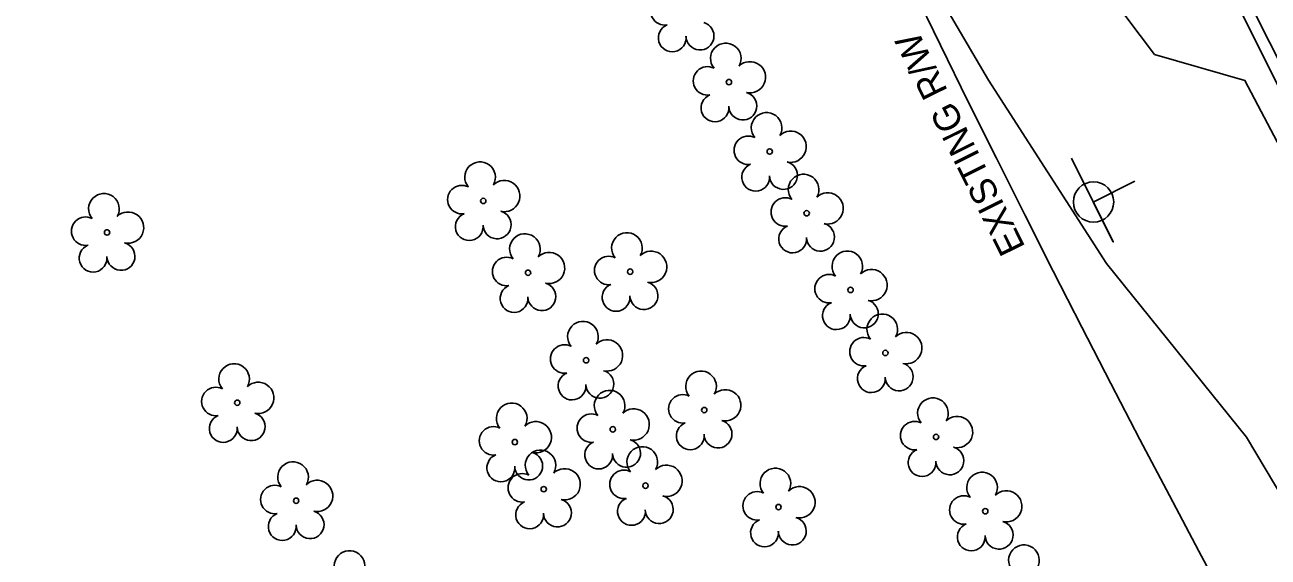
# Model space of a CAD drawing. Extents: x 472260 to 482161, y 489063 to 507124.
# Drawn here: x 478456.7 to 478607.7, y 494485.4 to 494550 of the extents above; entities that cross this region are included whole.
import ezdxf

# ---------------------------------------------------------------- set-up
doc = ezdxf.new("R2010")
doc.units = 0
for name, color, linetype in [('Exist Structure Minor Drop Inlet Cogo Elevation', 7, 'Continuous'), ('Exist Structure Minor Pipes CMP 15 Inch Cogo Point CELL', 7, 'Continuous'), ('Prop Drainage Structure Catch Basin Convert From Junction Box Label', 7, 'Continuous'), ('Prop Drainage Structure Drop Inlet Grate 2 Wide Slots and Flat Grates 840 20 Label', 7, 'Continuous'), ('Prop Drainage Structure Plot Symbol 50 Scale CELL', 7, 'Continuous'), ('Prop Drainage Structure Tops and Inverts LABEL', 7, 'Continuous'), ('Prop Earthen Structure Base Ditch Lateral Detail Label', 7, 'Continuous')]:
    doc.layers.add(name, color=color, linetype=linetype)

msp = doc.modelspace()

# ---------------------------------------------------------------- linework, layer by layer
at = {"layer": 'Exist Structure Minor Drop Inlet Cogo Elevation'}
for radius in [1948.89, 2048.89]:
    msp.add_arc((480407.9, 495448.91), radius, 192.1328, 219.63873, dxfattribs=at)
at = {"layer": 'Prop Drainage Structure Catch Basin Convert From Junction Box Label'}
msp.add_lwpolyline([(478849.64, 494173.84), (478834.24, 494192.77), (478817.97, 494213.7), (478799.94, 494237.17), (478784.01, 494258.57), (478764.88, 494285.24), (478750.33, 494305.9), (478735.16, 494328.74), (478719.56, 494353.09), (478700.76, 494382.7), (478681.8, 494413.94), (478670.09, 494433.69), (478651.57, 494465.89), (478635.82, 494494.36), (478621.81, 494520.92), (478610.22, 494543.28), (478596.37, 494570.77), (478587.24, 494590.09)], dxfattribs=at)
at = {"layer": 'Prop Drainage Structure Drop Inlet Grate 2 Wide Slots and Flat Grates 840 20 Label'}
for p, q in [((478542.25, 494543.02), (478542.25, 494543.02)), ((478547.2, 494534.6), (478547.2, 494534.6)), ((478512.41, 494528.6), (478512.41, 494528.6)), ((478551.69, 494527.1), (478551.69, 494527.1)), ((478466.71, 494524.77), (478466.71, 494524.77)), ((478530.25, 494520.01), (478530.25, 494520.01)), ((478517.85, 494519.88), (478517.85, 494519.88)), ((478557.02, 494517.79), (478557.02, 494517.79)), ((478561.25, 494510.14), (478561.25, 494510.14)), ((478524.9, 494509.25), (478524.9, 494509.25)), ((478482.52, 494504.1), (478482.52, 494504.1)), ((478539.25, 494503.21), (478539.25, 494503.21)), ((478528.14, 494500.87), (478528.14, 494500.87)), ((478516.24, 494499.32), (478516.24, 494499.32)), ((478567.41, 494499.95), (478567.41, 494499.95)), ((478519.75, 494493.61), (478519.75, 494493.61)), ((478532.11, 494494.03), (478532.11, 494494.03)), ((478489.68, 494492.2), (478489.68, 494492.2)), ((478548.27, 494491.43), (478548.27, 494491.43)), ((478573.39, 494490.93), (478573.39, 494490.93))]:
    msp.add_line(p, q, dxfattribs=at)
for centre in [(478542.25, 494543.02), (478547.2, 494534.6), (478512.41, 494528.6), (478551.69, 494527.1), (478466.71, 494524.77), (478517.85, 494519.88), (478530.25, 494520.01), (478557.02, 494517.79), (478524.9, 494509.25), (478561.25, 494510.14), (478482.52, 494504.1), (478539.25, 494503.21), (478528.14, 494500.87), (478516.24, 494499.32), (478567.41, 494499.95), (478532.11, 494494.03), (478519.75, 494493.61), (478489.68, 494492.2), (478548.27, 494491.43), (478573.39, 494490.93)]:
    msp.add_circle(centre, 0.326, dxfattribs=at)
for centre, radius, start, end in [((478534.46, 494551.67), 1.73, 62.6636, 279.3457), ((478538.73, 494548.62), 1.7, 181.2822, 74.56), ((478535.36, 494548.4), 1.69, 111.5671, 6.231), ((478541.87, 494545.89), 1.86, 330.1651, 219.7134), ((478539.65, 494543.17), 1.73, 62.6636, 279.3457), ((478544.8, 494543.61), 1.9, 257.1011, 134.1999), ((478540.55, 494539.9), 1.69, 111.5671, 6.231), ((478543.93, 494540.12), 1.7, 181.2822, 74.56), ((478546.82, 494537.47), 1.86, 330.1651, 219.7134), ((478549.75, 494535.18), 1.9, 257.1011, 134.1999), ((478544.6, 494534.75), 1.73, 62.6636, 279.3457), ((478512.02, 494531.48), 1.86, 330.1651, 219.7134), ((478545.5, 494531.47), 1.69, 111.5671, 6.231), ((478548.87, 494531.7), 1.7, 181.2822, 74.56), ((478514.95, 494529.19), 1.9, 257.1011, 134.1999), ((478551.31, 494529.98), 1.86, 330.1651, 219.7134), ((478466.33, 494527.64), 1.86, 330.1651, 219.7134), ((478509.8, 494528.76), 1.73, 62.6636, 279.3457), ((478554.24, 494527.69), 1.9, 257.1011, 134.1999), ((478549.09, 494527.26), 1.73, 62.6636, 279.3457), ((478464.11, 494524.92), 1.73, 62.6636, 279.3457), ((478469.26, 494525.36), 1.9, 257.1011, 134.1999), ((478510.7, 494525.48), 1.69, 111.5671, 6.231), ((478514.08, 494525.7), 1.7, 181.2822, 74.56), ((478517.46, 494522.75), 1.86, 330.1651, 219.7134), ((478529.86, 494522.88), 1.86, 330.1651, 219.7134), ((478549.99, 494523.98), 1.69, 111.5671, 6.231), ((478553.37, 494524.2), 1.7, 181.2822, 74.56), ((478465.01, 494521.65), 1.69, 111.5671, 6.231), ((478468.39, 494521.87), 1.7, 181.2822, 74.56), ((478515.24, 494520.03), 1.73, 62.6636, 279.3457), ((478520.4, 494520.46), 1.9, 257.1011, 134.1999), ((478527.64, 494520.16), 1.73, 62.6636, 279.3457), ((478532.8, 494520.6), 1.9, 257.1011, 134.1999), ((478556.63, 494520.66), 1.86, 330.1651, 219.7134), ((478559.57, 494518.38), 1.9, 257.1011, 134.1999), ((478519.52, 494516.98), 1.7, 181.2822, 74.56), ((478531.92, 494517.11), 1.7, 181.2822, 74.56), ((478554.41, 494517.94), 1.73, 62.6636, 279.3457), ((478516.15, 494516.75), 1.69, 111.5671, 6.231), ((478528.54, 494516.89), 1.69, 111.5671, 6.231), ((478555.31, 494514.67), 1.69, 111.5671, 6.231), ((478558.69, 494514.89), 1.7, 181.2822, 74.56), ((478524.51, 494512.12), 1.86, 330.1651, 219.7134), ((478560.87, 494513.01), 1.86, 330.1651, 219.7134), ((478563.8, 494510.73), 1.9, 257.1011, 134.1999), ((478522.29, 494509.41), 1.73, 62.6636, 279.3457), ((478527.44, 494509.84), 1.9, 257.1011, 134.1999), ((478558.65, 494510.29), 1.73, 62.6636, 279.3457), ((478482.14, 494506.97), 1.86, 330.1651, 219.7134), ((478526.57, 494506.35), 1.7, 181.2822, 74.56), ((478538.86, 494506.08), 1.86, 330.1651, 219.7134), ((478559.55, 494507.02), 1.69, 111.5671, 6.231), ((478562.93, 494507.24), 1.7, 181.2822, 74.56), ((478485.07, 494504.69), 1.9, 257.1011, 134.1999), ((478523.19, 494506.13), 1.69, 111.5671, 6.231), ((478479.92, 494504.25), 1.73, 62.6636, 279.3457), ((478527.75, 494503.74), 1.86, 330.1651, 219.7134), ((478536.64, 494503.36), 1.73, 62.6636, 279.3457), ((478541.8, 494503.79), 1.9, 257.1011, 134.1999), ((478515.86, 494502.2), 1.86, 330.1651, 219.7134), ((478567.03, 494502.83), 1.86, 330.1651, 219.7134), ((478480.82, 494500.98), 1.69, 111.5671, 6.231), ((478484.2, 494501.2), 1.7, 181.2822, 74.56), ((478525.53, 494501.02), 1.73, 62.6636, 279.3457), ((478530.68, 494501.46), 1.9, 257.1011, 134.1999), ((478540.92, 494500.31), 1.7, 181.2822, 74.56), ((478569.96, 494500.54), 1.9, 257.1011, 134.1999), ((478513.64, 494499.48), 1.73, 62.6636, 279.3457), ((478518.79, 494499.91), 1.9, 257.1011, 134.1999), ((478537.55, 494500.08), 1.69, 111.5671, 6.231), ((478564.81, 494500.11), 1.73, 62.6636, 279.3457), ((478526.43, 494497.75), 1.69, 111.5671, 6.231), ((478529.81, 494497.97), 1.7, 181.2822, 74.56), ((478514.54, 494496.2), 1.69, 111.5671, 6.231), ((478517.92, 494496.42), 1.7, 181.2822, 74.56), ((478519.36, 494496.49), 1.86, 330.1651, 219.7134), ((478531.72, 494496.91), 1.86, 330.1651, 219.7134), ((478565.71, 494496.83), 1.69, 111.5671, 6.231), ((478569.08, 494497.05), 1.7, 181.2822, 74.56), ((478489.3, 494495.07), 1.86, 330.1651, 219.7134), ((478522.3, 494494.2), 1.9, 257.1011, 134.1999), ((478529.5, 494494.19), 1.73, 62.6636, 279.3457), ((478534.66, 494494.62), 1.9, 257.1011, 134.1999), ((478547.89, 494494.3), 1.86, 330.1651, 219.7134), ((478492.23, 494492.79), 1.9, 257.1011, 134.1999), ((478517.14, 494493.77), 1.73, 62.6636, 279.3457), ((478573, 494493.8), 1.86, 330.1651, 219.7134), ((478487.08, 494492.35), 1.73, 62.6636, 279.3457), ((478545.67, 494491.58), 1.73, 62.6636, 279.3457), ((478550.82, 494492.02), 1.9, 257.1011, 134.1999), ((478570.78, 494491.08), 1.73, 62.6636, 279.3457), ((478575.93, 494491.52), 1.9, 257.1011, 134.1999), ((478518.04, 494490.49), 1.69, 111.5671, 6.231), ((478521.42, 494490.72), 1.7, 181.2822, 74.56), ((478530.41, 494490.91), 1.69, 111.5671, 6.231), ((478533.78, 494491.14), 1.7, 181.2822, 74.56), ((478487.98, 494489.08), 1.69, 111.5671, 6.231), ((478491.36, 494489.3), 1.7, 181.2822, 74.56), ((478546.57, 494488.31), 1.69, 111.5671, 6.231), ((478549.94, 494488.53), 1.7, 181.2822, 74.56), ((478571.68, 494487.81), 1.69, 111.5671, 6.231), ((478575.06, 494488.03), 1.7, 181.2822, 74.56), ((478578.08, 494484.98), 1.86, 330.1651, 219.7134), ((478496.16, 494484.27), 1.86, 330.1651, 219.7134)]:
    msp.add_arc(centre, radius, start, end, dxfattribs=at)
at = {"layer": 'Prop Drainage Structure Plot Symbol 50 Scale CELL'}
msp.add_lwpolyline([(478848.96, 494173.09), (478823.38, 494205.51), (478797.42, 494239.12), (478772.09, 494273.2), (478749.01, 494305.94), (478733.03, 494329.58), (478715.27, 494357.24), (478689.75, 494398.3), (478671.1, 494429.57), (478654.66, 494457.42), (478638.8, 494486.1), (478625.46, 494510.7), (478608.27, 494543.89), (478591.97, 494576.68), (478579.13, 494602.21), (478568.8, 494623)], dxfattribs=at)
at = {"layer": 'Prop Drainage Structure Tops and Inverts LABEL'}
msp.add_lwpolyline([(478623.26, 494469.49), (478605.12, 494499.9), (478588.1, 494520.99), (478573.76, 494543.26), (478559.5, 494567.63), (478567.36, 494574.63), (478572.8, 494574.41), (478593.95, 494546.36), (478604.93, 494543.22), (478641.84, 494473.22)], dxfattribs=at)
at = {"layer": 'Prop Earthen Structure Base Ditch Lateral Detail Label'}
msp.add_line((478586.53, 494528.47), (478586.53, 494528.47), dxfattribs=at)
msp.add_lwpolyline([(478583.86, 494533.77), (478588.93, 494523.63), (478586.51, 494528.46), (478591.55, 494531.01)], dxfattribs=at)
msp.add_circle((478586.54, 494528.47), 2.45, dxfattribs=at)

# ---------------------------------------------------------------- texts
at = {"layer": 'Exist Structure Minor Pipes CMP 15 Inch Cogo Point CELL'}
msp.add_text('EXISTING R/W', height=3.2, rotation=116.3984, dxfattribs=at).set_placement((478578.29, 494523))

doc.saveas('drawing.dxf')
